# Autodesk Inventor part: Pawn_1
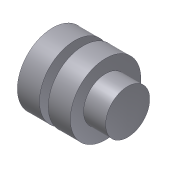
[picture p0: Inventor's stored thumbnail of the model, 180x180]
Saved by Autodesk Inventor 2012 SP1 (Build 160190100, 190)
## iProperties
Created: 2006-03
Part Number: Pawn_1
Document SubType Name: Modeling
Material: Stainless Steel, 440C
Density: 7.75 g/cm^3
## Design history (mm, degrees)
sketch "Sketch1"
  geometry: L1 (0, 0)-(5, 0); L2 (5, 0)-(5, 5); L3 (5, 5)-(0, 5); L4 (0, 5)-(0, 0); L5 (5, 8)-(10, 8); L6 (10, 8)-(10, 0); L7 (10, 0)-(5, 0); L8 (5, 0)-(5, 8); L9 (10, 5)-(12, 5); L10 (12, 5)-(12, 0); L11 (12, 0)-(10, 0); L12 (10, 0)-(10, 5); L13 (-5.1, 0)-(18.7, 0) reference; L14 (12, 8)-(17, 8); L15 (17, 8)-(17, 0); L16 (17, 0)-(12, 0); L17 (12, 0)-(12, 8)
  constraints: 32 end point, 8 parallel, 7 collinear, 4 horizontal, 4 perpendicular, 1 point on line
  dimensions: "d0" = 5 distance of L2.end L3.end; "d1" = 5 distance of L3.end L1.start; "d2" = 8 distance between parallel lines of L13 L5; "d3" = 2 distance of L9.start L9.end; "d4" = 5 distance of L14.start L14.end; "d5" = 5 distance between parallel lines of L9 L13
revolve "Revolution1" sketch "Sketch1" stored, may be unused: angle "d6" = 90 deg
body "Solid1"
